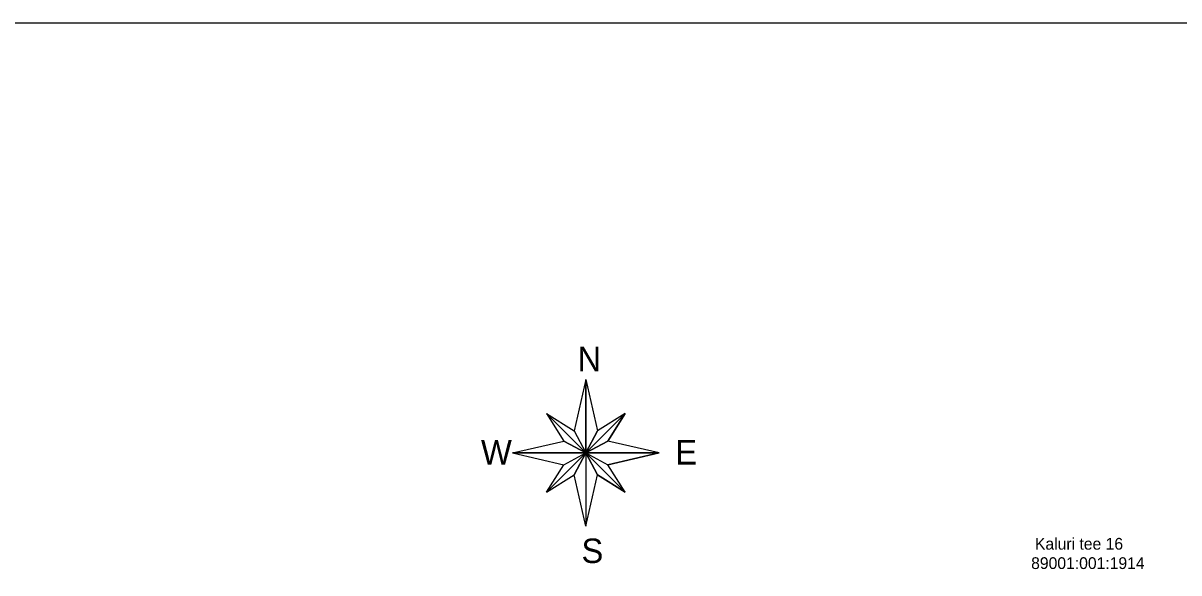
# Model space of a CAD drawing. Extents: x 546339 to 546593, y 6597108 to 6597251.
# Drawn here: x 546434.2 to 546503.1, y 6597218 to 6597250.7 of the extents above; entities that cross this region are included whole.
import ezdxf

# ---------------------------------------------------------------- set-up
doc = ezdxf.new("R2010")
doc.units = 0
doc.layers.add('PIIR', color=7, linetype='Continuous')
doc.layers.add('VORMISTUS', color=7, linetype='Continuous')

msp = doc.modelspace()

# ---------------------------------------------------------------- linework, layer by layer
at = {"layer": 'VORMISTUS'}
for p, q in [((546467.74, 6597229.473), (546467.04, 6597226.413)), ((546467.74, 6597229.473), (546468.44, 6597226.413)), ((546467.74, 6597229.473), (546467.74, 6597220.728)), ((546465.4, 6597227.448), (546470.09, 6597222.753)), ((546465.4, 6597227.448), (546467.04, 6597226.413)), ((546465.4, 6597227.448), (546466.43, 6597225.803)), ((546470.09, 6597227.448), (546465.4, 6597222.753)), ((546470.09, 6597227.448), (546468.44, 6597226.413)), ((546470.09, 6597227.448), (546469.055, 6597225.803)), ((546467.04, 6597226.413), (546467.74, 6597225.098)), ((546467.74, 6597225.098), (546468.44, 6597226.413)), ((546463.37, 6597225.098), (546466.43, 6597225.803)), ((546467.74, 6597225.098), (546466.43, 6597225.803)), ((546469.055, 6597225.803), (546467.74, 6597225.098)), ((546472.115, 6597225.098), (546469.055, 6597225.803)), ((546463.37, 6597225.098), (546466.43, 6597224.398)), ((546463.37, 6597225.098), (546472.115, 6597225.098)), ((546466.43, 6597224.398), (546467.74, 6597225.098)), ((546467.74, 6597225.098), (546467.04, 6597223.788)), ((546467.74, 6597225.098), (546469.055, 6597224.398)), ((546468.44, 6597223.788), (546467.74, 6597225.098)), ((546472.115, 6597225.098), (546469.055, 6597224.398)), ((546465.4, 6597222.753), (546466.43, 6597224.398)), ((546470.09, 6597222.753), (546469.055, 6597224.398)), ((546465.4, 6597222.753), (546467.04, 6597223.788)), ((546467.74, 6597220.728), (546467.04, 6597223.788)), ((546467.74, 6597220.728), (546468.44, 6597223.788)), ((546470.09, 6597222.753), (546468.44, 6597223.788))]:
    msp.add_line(p, q, dxfattribs=at)
for points in [[(546593.177, 6597250.72), (546339.379, 6597250.72), (546339.379, 6597108.37), (546593.177, 6597108.37)], [(546467.74, 6597229.473), (546468.44, 6597226.413), (546467.74, 6597225.098)], [(546465.4, 6597227.448), (546467.04, 6597226.413), (546467.74, 6597225.098)], [(546467.74, 6597225.098), (546469.055, 6597225.803), (546470.09, 6597227.448)], [(546463.37, 6597225.098), (546466.43, 6597225.803), (546467.74, 6597225.098)], [(546465.4, 6597222.753), (546466.43, 6597224.398), (546467.74, 6597225.098)], [(546467.74, 6597220.728), (546467.04, 6597223.788), (546467.74, 6597225.098)], [(546467.74, 6597225.098), (546468.44, 6597223.788), (546470.09, 6597222.753)], [(546467.74, 6597225.098), (546469.055, 6597224.398), (546472.115, 6597225.098)]]:
    msp.add_lwpolyline(points, close=True, dxfattribs=at)

# ---------------------------------------------------------------- texts
at = {"layer": 'PIIR'}
for s, p in [('Kaluri tee 16', (546494.526, 6597219.334)), ('89001:001:1914', (546494.298, 6597218.181))]:
    msp.add_text(s, height=0.7, dxfattribs=at).set_placement(p)
at = {"layer": 'VORMISTUS'}
for s, p in [('N', (546467.245, 6597229.973)), ('W', (546461.485, 6597224.408)), ('E', (546473.08, 6597224.408)), ('S', (546467.48, 6597218.538))]:
    msp.add_text(s, height=1.458, dxfattribs=at).set_placement(p)

doc.saveas('drawing.dxf')
